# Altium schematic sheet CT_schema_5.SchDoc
size 283 x 147 mm
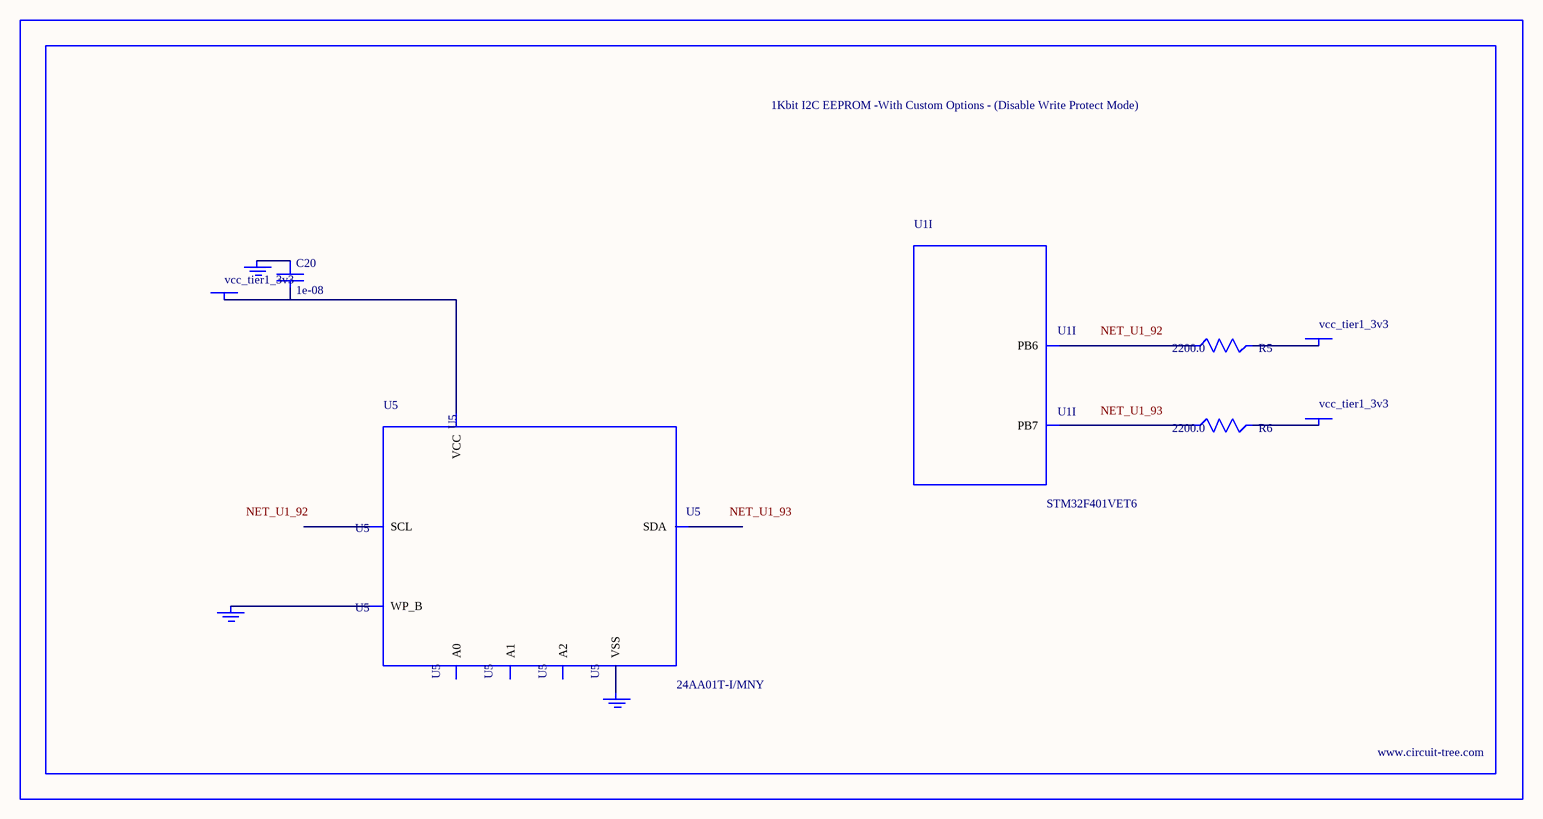
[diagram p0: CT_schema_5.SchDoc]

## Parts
BORDER4  (no value)
C20  1e-08  [C0402]
GND_INSTANCE_4_0  (no value)
GND_INSTANCE_4_1  (no value)
GND_INSTANCE_4_2  (no value)
POWER_INSTANCE_4_0  vcc_tier1_3v3
POWER_INSTANCE_4_1  vcc_tier1_3v3
POWER_INSTANCE_4_2  vcc_tier1_3v3
R5  2200.0  [R0603]
R6  2200.0  [R0603]
U1  STM32F401VET6  [LQFP100]  (part I of 10)
U5  24AA01T-I/MNY  [TDFN-8/6MM]

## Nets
NetC20_1: C20.1 GND_INSTANCE_4_1.0(GND)
NetC20_2: C20.2 POWER_INSTANCE_4_0.0(PWR) U5.8(VCC)
NetGND_INSTANCE_4_0_0: GND_INSTANCE_4_0.0(GND) U5.7(WP_B)
NetGND_INSTANCE_4_2_0: GND_INSTANCE_4_2.0(GND) U5.4(VSS)
NetPOWER_INSTANCE_4_1_0: POWER_INSTANCE_4_1.0(PWR) R5.2
NetPOWER_INSTANCE_4_2_0: POWER_INSTANCE_4_2.0(PWR) R6.2
NetR5_1: R5.1 U1.92(PB6)
NetR6_1: R6.1 U1.93(PB7)

Not connected (* = marked no-connect by the designer): U5 1(A0) 2(A1) 3(A2) 5(SDA) 6(SCL)

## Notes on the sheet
- Labels drawn without touching a wire or pin: NET_U1_92, NET_U1_93

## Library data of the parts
BORDER4 = BORDER_PAGE4
C20 = C0402C103K3RAC
GND_INSTANCE_4_0-GND_INSTANCE_4_2 = GND
POWER_INSTANCE_4_0-POWER_INSTANCE_4_2 = PWR
R5 R6 = RC0603JR-072K2L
